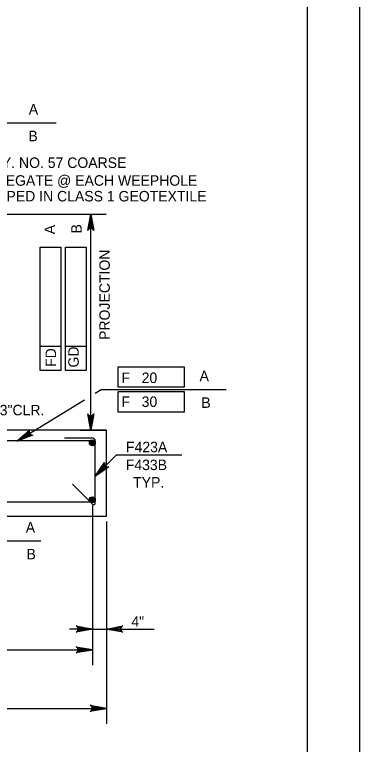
# Model space of a CAD drawing. Extents: x 638255 to 640306, y 296059 to 298435.
# Drawn here: x 640018.7 to 640117.5, y 298119.9 to 298328.7 of the extents above; entities that cross this region are included whole.
import ezdxf

# ---------------------------------------------------------------- set-up
doc = ezdxf.new("R2010")
doc.units = 0
for name, color, linetype in [('2', 7, 'Continuous'), ('Level 3', 7, 'Continuous'), ('Level 4', 7, 'Continuous'), ('Level 5', 7, 'Continuous'), ('Level 6', 7, 'Continuous'), ('Level 9', 7, 'Continuous'), ('PLT-BNDY', 7, 'Continuous')]:
    doc.layers.add(name, color=color, linetype=linetype)

msp = doc.modelspace()

# ---------------------------------------------------------------- linework, layer by layer
at = {"layer": '2'}
msp.add_line((640102.46, 298420.46), (640102.46, 297856.46), dxfattribs=at)
at = {"layer": 'Level 4'}
for p, q in [((639997.81, 298297.7), (640030.53, 298297.7)), ((639996.17, 298271.6), (640044.89, 298271.6)), ((640040.48, 298209.79), (640040.48, 298271.6)), ((640026.01, 298226.88), (640026.01, 298262.11)), ((640026.01, 298262.11), (640031.9, 298262.11)), ((640031.9, 298262.11), (640031.9, 298226.88)), ((640033.28, 298226.88), (640033.28, 298262.11)), ((640033.28, 298262.11), (640039.17, 298262.11)), ((640039.17, 298262.11), (640039.17, 298226.88)), ((640031.9, 298233.71), (640026.01, 298233.71)), ((640039.17, 298233.71), (640033.28, 298233.71)), ((640048.31, 298227.95), (640067.21, 298227.95)), ((640048.31, 298222.05), (640048.31, 298227.95)), ((640067.21, 298227.95), (640067.21, 298222.05)), ((640031.9, 298226.88), (640026.01, 298226.88)), ((640039.17, 298226.88), (640033.28, 298226.88)), ((640041.71, 298220.33), (640043.5, 298221.43)), ((640043.5, 298221.43), (640079.3, 298221.43)), ((640067.21, 298222.05), (640048.31, 298222.05)), ((640048.31, 298220.85), (640067.21, 298220.85)), ((640048.31, 298214.95), (640048.31, 298220.85)), ((640067.21, 298220.85), (640067.21, 298214.95)), ((640019.49, 298206.72), (640038.66, 298218.46)), ((640067.21, 298214.95), (640048.31, 298214.95)), ((640037.31, 298209.79), (640044.9, 298209.79)), ((640041.79, 298196.65), (640047.86, 298202.7)), ((640047.86, 298202.7), (640066.61, 298202.7)), ((640040.94, 298188.24), (640040.94, 298142.57)), ((640045, 298183.7), (640045, 298125.8)), ((639994.17, 298178.11), (640026.22, 298178.11)), ((640045, 298163.43), (640045, 298151.96)), ((640040.94, 298152.91), (640034.36, 298152.91)), ((640040.94, 298152.91), (640058.69, 298152.91)), ((639935, 298146.99), (640040.94, 298146.99)), ((639930.94, 298130.22), (640045, 298130.22))]:
    msp.add_line(p, q, dxfattribs=at)
for points in [[(640040.48, 298271.6), (640041.35, 298266.95), (640041.1, 298267.31), (640040.79, 298267.49), (640040.48, 298267.55), (640040.16, 298267.49), (640039.85, 298267.31), (640039.61, 298266.95), (640040.48, 298271.6), (640039.85, 298267.31), (640040.16, 298267.49), (640040.48, 298271.6), (640040.48, 298267.55), (640040.79, 298267.49), (640040.48, 298271.6), (640041.1, 298267.31)], [(640040.48, 298209.79), (640039.61, 298214.45), (640039.85, 298214.09), (640040.16, 298213.9), (640040.48, 298213.85), (640040.79, 298213.9), (640041.1, 298214.09), (640041.35, 298214.45), (640040.48, 298209.79), (640041.1, 298214.09), (640040.79, 298213.9), (640040.48, 298209.79), (640040.48, 298213.85), (640040.16, 298213.9), (640040.48, 298209.79), (640039.85, 298214.09)], [(640019.49, 298206.72), (640023, 298209.9), (640022.83, 298209.5), (640022.83, 298209.13), (640022.95, 298208.84), (640023.16, 298208.6), (640023.48, 298208.43), (640023.91, 298208.41), (640019.49, 298206.72), (640023.48, 298208.43), (640023.16, 298208.6), (640019.49, 298206.72), (640022.95, 298208.84), (640022.83, 298209.13), (640019.49, 298206.72), (640022.83, 298209.5)], [(640041.79, 298196.65), (640044.47, 298200.55), (640044.39, 298200.12), (640044.48, 298199.77), (640044.66, 298199.51), (640044.92, 298199.33), (640045.27, 298199.24), (640045.7, 298199.31), (640041.79, 298196.65), (640045.27, 298199.24), (640044.92, 298199.33), (640041.79, 298196.65), (640044.66, 298199.51), (640044.48, 298199.77), (640041.79, 298196.65), (640044.39, 298200.12)], [(640040.94, 298152.91), (640036.29, 298152.04), (640036.65, 298152.29), (640036.83, 298152.6), (640036.89, 298152.91), (640036.83, 298153.22), (640036.65, 298153.53), (640036.29, 298153.78), (640040.94, 298152.91), (640036.65, 298153.53), (640036.83, 298153.22), (640040.94, 298152.91), (640036.89, 298152.91), (640036.83, 298152.6), (640040.94, 298152.91), (640036.65, 298152.29)], [(640045, 298152.91), (640049.65, 298153.78), (640049.29, 298153.53), (640049.11, 298153.22), (640049.05, 298152.91), (640049.11, 298152.6), (640049.29, 298152.29), (640049.65, 298152.04), (640045, 298152.91), (640049.29, 298152.29), (640049.11, 298152.6), (640045, 298152.91), (640049.05, 298152.91), (640049.11, 298153.22), (640045, 298152.91), (640049.29, 298153.53)], [(640040.94, 298146.99), (640036.29, 298146.12), (640036.65, 298146.36), (640036.83, 298146.68), (640036.89, 298146.99), (640036.83, 298147.3), (640036.65, 298147.61), (640036.29, 298147.86), (640040.94, 298146.99), (640036.65, 298147.61), (640036.83, 298147.3), (640040.94, 298146.99), (640036.89, 298146.99), (640036.83, 298146.68), (640040.94, 298146.99), (640036.65, 298146.36)], [(640045, 298130.22), (640040.35, 298129.35), (640040.7, 298129.59), (640040.89, 298129.91), (640040.94, 298130.22), (640040.89, 298130.53), (640040.7, 298130.84), (640040.35, 298131.09), (640045, 298130.22), (640040.7, 298130.84), (640040.89, 298130.53), (640045, 298130.22), (640040.94, 298130.22), (640040.89, 298129.91), (640045, 298130.22), (640040.7, 298129.59)]]:
    msp.add_lwpolyline(points, dxfattribs=at)
for points in [[(640039.98, 298268.65), (640040.97, 298268.65), (640040.48, 298271.6)], [(640039.98, 298212.74), (640040.97, 298212.74), (640040.48, 298209.79)], [(640022.21, 298207.81), (640021.69, 298208.65), (640019.44, 298206.69)], [(640044.32, 298198.48), (640043.63, 298199.18), (640041.89, 298196.75)], [(640037.86, 298152.42), (640037.86, 298153.4), (640040.81, 298152.91)], [(640048.22, 298153.4), (640048.22, 298152.42), (640045.27, 298152.91)], [(640037.99, 298147.48), (640037.99, 298146.5), (640040.94, 298146.99)], [(640042.05, 298130.71), (640042.05, 298129.73), (640045, 298130.22)]]:
    msp.add_lwpolyline(points, close=True, dxfattribs=at)
at = {"layer": 'Level 5'}
for p, q in [((640041.01, 298209.79), (640041.01, 298209.79)), ((640044.76, 298209.79), (640044.76, 298209.79))]:
    msp.add_line(p, q, dxfattribs=at)
at = {"layer": 'Level 6'}
for p, q in [((640041.78, 298206.72), (639934.16, 298206.72)), ((640032.93, 298207.62), (640040.77, 298207.62)), ((640041.79, 298189.04), (640041.79, 298206.59)), ((640035.22, 298194.37), (640040.92, 298188.68)), ((639934.15, 298189.32), (640041.79, 298189.32))]:
    msp.add_line(p, q, dxfattribs=at)
for centre, radius in [((640040.94, 298206.16), 0.832), ((640040.94, 298206.16), 0.624), ((640040.94, 298206.16), 0.416), ((640040.94, 298206.16), 0.208), ((640040.94, 298189.91), 0.832), ((640040.94, 298189.91), 0.624), ((640040.94, 298189.91), 0.416), ((640040.94, 298189.91), 0.208)]:
    msp.add_circle(centre, radius, dxfattribs=at)
for centre, radius, start, end in [((640040.77, 298206.59), 1.02, 0, 90), ((640041.28, 298189.04), 0.511, 225, 0)]:
    msp.add_arc(centre, radius, start, end, dxfattribs=at)
at = {"layer": 'Level 9'}
for p, q in [((640045, 298209.79), (639991.46, 298209.79)), ((640045, 298185.23), (640045, 298209.79)), ((639930.94, 298185.23), (640045, 298185.23))]:
    msp.add_line(p, q, dxfattribs=at)
at = {"layer": 'PLT-BNDY'}
msp.add_lwpolyline([(639276.46, 298435.46), (640117.46, 298435.46), (640117.46, 297841.46), (639276.46, 297841.46)], close=True, dxfattribs=at)

# ---------------------------------------------------------------- texts
at = {"layer": 'Level 3'}
for s, height, p in [('1/2 C.Y. NO. 57 COARSE', 3.0001, (640004.32, 298284.8)), ('3"CLR.', 3, (640014.41, 298214.04)), ('4"', 3, (640052.12, 298153.56))]:
    msp.add_text(s, height=height, dxfattribs=at).set_placement(p)
at = {"layer": 'Level 4'}
for s, height, p in [('A', 3, (640022.73, 298300.07)), ('B', 3, (640022.63, 298292.44)), ('AGGREGATE @ EACH WEEPHOLE', 3.0001, (640004.31, 298279.71)), ('WRAPPED IN CLASS 1 GEOTEXTILE', 3.0001, (640004.31, 298275.22)), ('F   20', 3, (640049.28, 298223.28)), ('A', 3, (640071.66, 298223.81)), ('F   30', 3, (640049.28, 298216.44)), ('B', 3, (640072.16, 298216.17)), ('F423A', 3, (640050.58, 298203.48)), ('F433B', 3, (640050.52, 298198.37)), ('TYP.', 3, (640052.63, 298193.38)), ('A', 3, (640021.86, 298180.48)), ('B', 3, (640022.09, 298172.85))]:
    msp.add_text(s, height=height, dxfattribs=at).set_placement(p)
for s, p in [('A', (640030.25, 298265.84)), ('B', (640037.88, 298266.07)), ('PROJECTION', (640045.95, 298235.6)), ('GD', (640037.05, 298227.71)), ('FD', (640030.55, 298227.9))]:
    msp.add_text(s, height=3, rotation=90, dxfattribs=at).set_placement(p)

doc.saveas('drawing.dxf')
